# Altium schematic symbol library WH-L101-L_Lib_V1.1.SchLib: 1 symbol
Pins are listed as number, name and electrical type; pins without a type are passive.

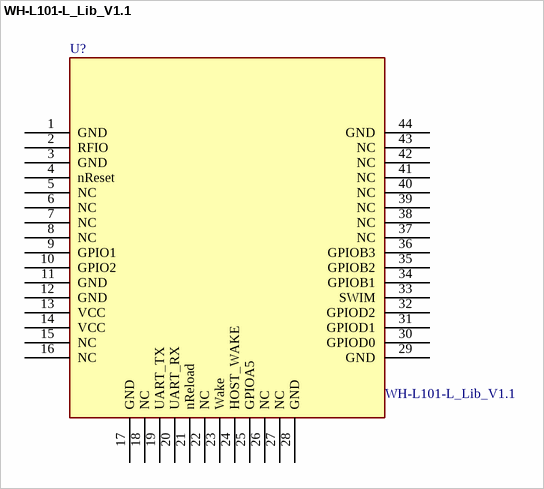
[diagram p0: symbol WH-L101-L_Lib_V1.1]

## WH-L101-L_Lib_V1.1
designator U?
footprint WH-L101-SMT-V1.0 (Footprint not found)
pins: 1 GND, 2 RFIO, 3 GND, 4 nReset, 5 NC, 6 NC, 7 NC, 8 NC, 9 GPIO1, 10 GPIO2, 11 GND, 12 GND, 13 VCC, 14 VCC, 15 NC, 16 NC, 17 GND, 18 NC, 19 UART_TX, 20 UART_RX, 21 nReload, 22 NC, 23 Wake, 24 HOST_WAKE, 25 GPIOA5, 26 NC, 27 NC, 28 GND, 29 GND, 30 GPIOD0, 31 GPIOD1, 32 GPIOD2, 33 SWIM, 34 GPIOB1, 35 GPIOB2, 36 GPIOB3, 37 NC, 38 NC, 39 NC, 40 NC, 41 NC, 42 NC, 43 NC, 44 GND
